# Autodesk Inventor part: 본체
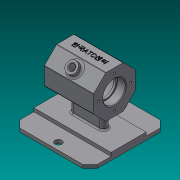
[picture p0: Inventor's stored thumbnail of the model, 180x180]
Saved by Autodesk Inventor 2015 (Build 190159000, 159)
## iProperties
Created: 2018-06
Part Number: 본체
Material: 일반
Document SubType Name: Modeling
Designer: Administrator
Density: 1 g/cm^3
Appearance: 기본값
Mass: 204.444 g
Surface Area: 601.935 cm^2
Volume: 204.444 cm^3
Author: Administrator
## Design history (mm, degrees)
sketch "스케치1"
  geometry: L1 (-55, 55)-(55, 55); L2 (55, 55)-(55, -55); L3 (55, -55)-(-55, -55); L4 (-55, -55)-(-55, 55); L5 (-55, 55)-(55, -55); L6 (55, 55)-(-55, -55); 1 further point
  constraints: 12 end point, 2 midpoint, 2 parallel, 1 horizontal, 1 perpendicular
  dimensions: "d0" = 110 distance of L1.end L2.end; "d1" = 110 distance of L1.start L1.end
extrude "돌출1" new body sketch "스케치1" distance "d2" = 5; taper "d3" = 0 deg
sketch "스케치2"
  geometry: L1 (55, 55)-(-55, 55) reference; L2 (-55, 55)-(-55, -55) reference; L3 (-55, -55)-(55, -55) reference; L4 (55, -55)-(55, 55) reference; L5 (55, -25)-(-55, -25); L6 (-55, -25)-(-55, 25); L7 (-55, 25)-(55, 25); L8 (55, 25)-(55, -25); L9 (55, -25)-(-55, 25); L10 (-55, -25)-(55, 25); 1 further point
  constraints: 12 end point, 2 midpoint, 2 parallel, 1 horizontal, 1 perpendicular, 1 point on line
  dimensions: "d4" = 30 distance between parallel lines of L7 L1
extrude "돌출2" join sketch "스케치2" distance "d5" = 5; taper "d6" = 0 deg
sketch "스케치3"
  geometry: L1 (-30, 49.574)-(-30, 74.426); L2 (-30, 74.426)-(-12.426, 92); L3 (-12.426, 92)-(12.426, 92); L4 (12.426, 92)-(30, 74.426); L5 (30, 74.426)-(30, 49.574); L6 (30, 49.574)-(12.426, 32); L7 (12.426, 32)-(-12.426, 32); L8 (-12.426, 32)-(-30, 49.574); L9 (55, 0)-(-55, 0) reference; 3 further points
  constraints: 16 end point, 1 midpoint, 1 parallel, 1 vertical alignment, 17 other
  dimensions: "d7" = 62 distance from line of L9 point (0, 62); "d8" = 60 distance between parallel lines of L1 L5
extrude "돌출3" join sketch "스케치3" stored distance "d9" = 70; taper "d10" = 0 deg
sketch "스케치4"
  geometry: L1 (-19, 0)-(19, 0); L2 (-19, -5)-(19, -5); L3 (19, 5)-(-19, 5); A1 r 5 centre (-19, 0) between (-19, 5) and (-19, -5); A2 r 5 centre (19, 0) between (19, -5) and (19, 5); 2 further points
  constraints: 8 end point, 4 point on circle, 4 tangent, 2 centre point, 1 coincident, 1 horizontal, 1 midpoint, 1 parallel
  dimensions: "d11" = 38 distance of L1.end L1.start; "d12" = 5 radius of A2
extrude "돌출4" join sketch "스케치4" stored distance "d13" = 70; taper "d14" = 0 deg
sketch "스케치5"
  geometry: L1 (35, 74.426)-(35, 49.574) reference; L2 (35, 62)-(-35, 62); L3 (-35, 49.574)-(-35, 74.426) reference; L4 (35, 92)-(35, 74.426) reference; L5 (-35, 74.426)-(-35, 92) reference; L6 (35, 78)-(23.3, 78); L7 (23, 77.7)-(23, 76); L8 (23, 76)-(20, 76); L9 (20, 76)-(20, 84); L10 (17, 87)-(-17, 87); L11 (-20, 84)-(-20, 76); L12 (-20, 76)-(-23, 76); L13 (-23, 76)-(-23, 77.7); L14 (-23.3, 78)-(-35, 78); A1 r 0.3 centre (23.3, 77.7) between (23.3, 78) and (23, 77.7); A2 r 0.3 centre (-23.3, 77.7) between (-23, 77.7) and (-23.3, 78); A3 r 3 centre (17, 84) between (20, 84) and (17, 87); A4 r 3 centre (-17, 84) between (-17, 87) and (-20, 84); 1 further point
  constraints: 20 end point, 8 perpendicular, 8 point on circle, 8 tangent, 4 centre point, 2 collinear, 2 equal radius, 2 midpoint, 2 point on line, 1 horizontal
  dimensions: "d15" = 32 diameter of L6 L2; "d16" = 28 diameter of L8 L2; "d17" = 50 diameter of L10 L2; "d18" = 12 distance between parallel lines of L4 L7; "d19" = 3 distance between parallel lines of L9 L7; "d20" = 12 distance between parallel lines of L3 L13; "d21" = 3 distance between parallel lines of L13 L11; "d22" = 0.3 radius of A1; "d23" = 3 radius of A3
revolve "회전1" sketch "스케치5" stored, may be unused: angle "d24" = 90 deg
chamfer "모따기1" distance "d25" = 10; stored, may be unused: second distance "d26" = 2, angle "d27" = 45 deg
sketch "스케치6"
  geometry: L1 (0, -3.574)-(0, 28.426) reference; C1 r 8 at (35, 12.426); C2 r 4 at (35, 12.426); 2 further points
  constraints: 2 centre point, 1 horizontal alignment, 1 midpoint
  dimensions: "d28" = 35 distance from line of C1.centre L1; "d29" = 16 diameter of C1; "d30" = 8 diameter of C2
extrude "돌출5" join sketch "스케치6" distance "d31" = 7; taper "d32" = 0 deg
extrude "돌출6" cut sketch "스케치6" distance "d33" = 10; taper "d35" = 0 deg; dims "d34" = 10, "d36" = 0
chamfer "모따기2" distance "d37" = 1; stored, may be unused: second distance "d38" = 2, angle "d39" = 45 deg
sketch "스케치7"
  geometry: L1 (0, 0)-(0, 24.853) reference; L2 (70, 42.426)-(0, 42.426) reference; 2 further points
  constraints: 1 other
  dimensions: "d40" = 35 distance from line of L1 point (35, 12.426); "d41" = 30 distance from line of point (35, 12.426) L2
feature "엠보싱1" sketch "스케치7" dims "d0" = 110, "d1" = 110, "d42" = 0.5, "d43" = 0
sketch "스케치8"
  geometry: L1 (-45, 55)-(45, 55) reference; C1 r 5 at (0, 45); 1 further point
  constraints: 1 centre point, 1 vertical alignment
  dimensions: "d44" = 10 distance from line of L1 C1.centre; "d45" = 10 diameter of C1
extrude "돌출7" cut sketch "스케치8" stored distance "d46" = 0; taper "d47" = 0 deg
fillet "모깎기1" dims "d48" = 2
fillet "모깎기2" dims "d49" = 1
sketch "스케치9"
  geometry: C1 r 17 at (62, 0) reference; 2 further points
  constraints: 1 horizontal alignment
  dimensions: "d50" = 23 distance of C1.centre point (85, 0)
hole "구멍1" sketch "스케치9" at (85, 0) diameter "d51" = 3.242; stored, may be unused: countersink angle "d55" = 90 deg, drill point angle "d57" = 118 deg; dims "d52" = 8, "d53" = 4, "d54" = 2, "d56" = 10
fillet "모깎기3" dims "d61" = 3
chamfer "모따기3" distance "d62" = 1; stored, may be unused: second distance "d63" = 2, angle "d64" = 45 deg
node "솔리드1"
mirror "대칭1"
pattern_circular "원형 패턴1" dims angle "d59" = 360 deg
mirror "대칭2"
node "투영된 루프1"
